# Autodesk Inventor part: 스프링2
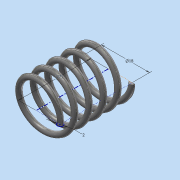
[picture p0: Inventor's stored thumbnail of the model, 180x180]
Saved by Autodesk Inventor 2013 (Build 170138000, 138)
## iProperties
Created: 2016-10
Part Number: 스프링2
Material: 강철, 탄소
Document SubType Name: Modeling
Designer: user
Mass: 6.88075 g
Surface Area: 17.7314 cm^2
Volume: 0.874302 cm^3
Density: 7.87 g/cm^3
Author: user
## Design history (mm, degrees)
sketch "스케치1"
  geometry: L1 (0, 0)-(9, 0); L2 (9, 0)-(9, 26); L3 (9, 26)-(0, 26); L4 (0, 26)-(0, 0); C1 r 1 at (9, 0)
  constraints: 8 end point, 2 parallel, 1 centre point, 1 coincident, 1 horizontal, 1 perpendicular
  dimensions: "d0" = 26 distance of L3.end L1.start (derived); "d1" = 18 diameter of L2 L4; "d2" = 2 diameter of C1
feature "코일1" pitch "d3" = 10; turns "d5" = 5; dims "d4" = 26 (= d0), "d6" = 0, angle "d7" = 90 deg, angle "d8" = 90 deg, "d9" = 0, "d10" = 0
sketch "스케치2"
  geometry: L1 (-8, 0)-(-10, 0) reference; 1 further point
  constraints: 1 horizontal alignment
extrude "돌출1" cut sketch "스케치2" distance "d11" = 10; taper "d12" = 0 deg
node "작업 평면1"
sketch "스케치3"
  geometry: L1 (-1, 0)-(1, 0) reference; 1 further point
  constraints: 1 horizontal alignment
extrude "돌출2" cut sketch "스케치3" distance "d14" = 10; taper "d15" = 0 deg
node "솔리드1"
node "절단 모서리 투영1"
node "절단 모서리 투영2"
other parameters: "d13" = 0
